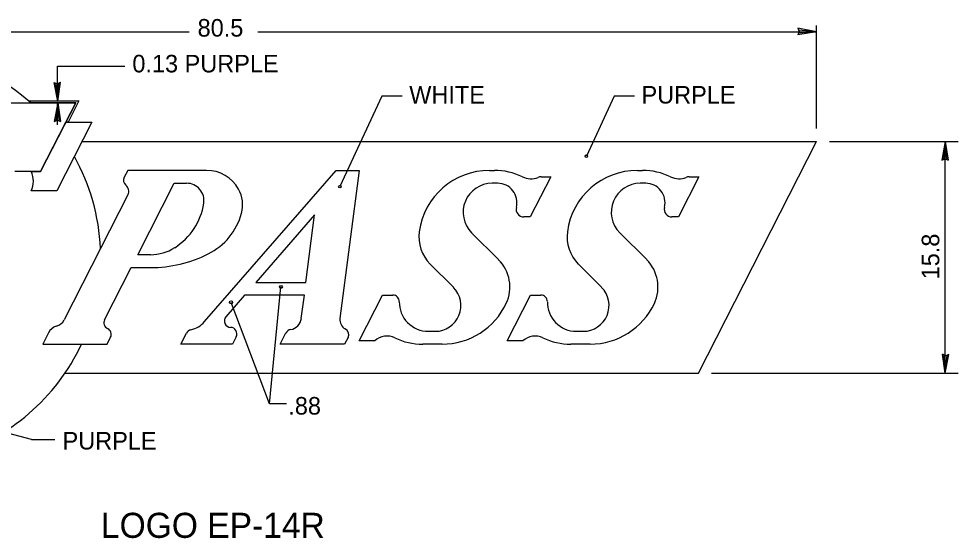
# Model space of a CAD drawing. Extents: x 10268197 to 10268826, y 2141503 to 2142677.
# Drawn here: x 10268696.97 to 10268729.24, y 2142372.5 to 2142390.35 of the extents above; entities that cross this region are included whole.
import ezdxf

# ---------------------------------------------------------------- set-up
doc = ezdxf.new("R2010")
doc.units = 0
for name, color, linetype in [('1', 7, 'Continuous'), ('Default', 7, 'Continuous'), ('TextDetails', 7, 'Continuous')]:
    doc.layers.add(name, color=color, linetype=linetype)

msp = doc.modelspace()

# ---------------------------------------------------------------- linework, layer by layer
at = {"layer": '1'}
for p, q in [((10268724.378, 2142386.58), (10268724.378, 2142390.119)), ((10268679.621, 2142389.898), (10268702.823, 2142389.898)), ((10268705.178, 2142389.898), (10268724.378, 2142389.898)), ((10268698.301, 2142388.721), (10268700.608, 2142388.721)), ((10268698.301, 2142387.55), (10268698.301, 2142388.721)), ((10268698.301, 2142386.707), (10268698.301, 2142387.47)), ((10268709.441, 2142387.689), (10268708.001, 2142384.581)), ((10268710.143, 2142387.689), (10268709.441, 2142387.689)), ((10268717.421, 2142387.689), (10268716.467, 2142385.63)), ((10268718.124, 2142387.689), (10268717.421, 2142387.689)), ((10268724.82, 2142386.137), (10268729.245, 2142386.137)), ((10268728.802, 2142378.174), (10268728.802, 2142386.137)), ((10268705.586, 2142377.117), (10268705.973, 2142381.135)), ((10268705.586, 2142377.117), (10268704.258, 2142380.606)), ((10268720.762, 2142378.174), (10268729.245, 2142378.174)), ((10268706.159, 2142377.117), (10268705.586, 2142377.117)), ((10268697.402, 2142375.891), (10268695.13, 2142376.486)), ((10268697.402, 2142375.891), (10268698.203, 2142375.891))]:
    msp.add_line(p, q, dxfattribs=at)
for centre, radius in [((10268716.467, 2142385.63), 0.0442), ((10268708.001, 2142384.581), 0.0442), ((10268705.973, 2142381.136), 0.0518), ((10268704.258, 2142380.606), 0.0518)]:
    msp.add_circle(centre, radius, dxfattribs=at)
at = {"layer": 'Default'}
for p, q in [((10268724.378, 2142389.898), (10268723.735, 2142390.023)), ((10268723.735, 2142390.023), (10268723.782, 2142389.908)), ((10268724.378, 2142389.898), (10268723.759, 2142389.963)), ((10268723.782, 2142389.908), (10268723.731, 2142389.795)), ((10268724.378, 2142389.898), (10268723.731, 2142389.795)), ((10268724.378, 2142389.898), (10268723.758, 2142389.855)), ((10268698.302, 2142387.519), (10268698.178, 2142388.162)), ((10268698.178, 2142388.162), (10268698.292, 2142388.114)), ((10268698.302, 2142387.519), (10268698.238, 2142388.137)), ((10268698.292, 2142388.114), (10268698.405, 2142388.166)), ((10268698.302, 2142387.519), (10268698.405, 2142388.166)), ((10268698.302, 2142387.519), (10268698.346, 2142388.138)), ((10268691.401, 2142387.465), (10268698.922, 2142387.465)), ((10268697.306, 2142387.531), (10268699.03, 2142387.531)), ((10268698.922, 2142387.465), (10268697.717, 2142385.099)), ((10268698.302, 2142387.466), (10268698.178, 2142386.823)), ((10268698.302, 2142387.466), (10268698.238, 2142386.848)), ((10268698.302, 2142387.466), (10268698.405, 2142386.819)), ((10268698.302, 2142387.466), (10268698.346, 2142386.847)), ((10268699.03, 2142387.531), (10268698.658, 2142386.801)), ((10268697.716, 2142385.097), (10268698.585, 2142386.801)), ((10268697.716, 2142385.097), (10268698.585, 2142386.801)), ((10268698.178, 2142386.823), (10268698.292, 2142386.87)), ((10268699.478, 2142386.801), (10268698.273, 2142384.435)), ((10268699.478, 2142386.801), (10268698.273, 2142384.435)), ((10268698.292, 2142386.87), (10268698.405, 2142386.819)), ((10268698.585, 2142386.801), (10268699.478, 2142386.801)), ((10268698.585, 2142386.801), (10268699.478, 2142386.801)), ((10268699.139, 2142386.137), (10268724.378, 2142386.137)), ((10268720.32, 2142378.174), (10268724.378, 2142386.137)), ((10268728.802, 2142386.137), (10268728.677, 2142385.495)), ((10268728.802, 2142386.137), (10268728.737, 2142385.519)), ((10268728.802, 2142386.137), (10268728.905, 2142385.49)), ((10268728.802, 2142386.137), (10268728.846, 2142385.518)), ((10268728.677, 2142385.495), (10268728.792, 2142385.542)), ((10268728.792, 2142385.542), (10268728.905, 2142385.49)), ((10268700.708, 2142385.142), (10268700.587, 2142384.906)), ((10268703.417, 2142385.142), (10268700.708, 2142385.142)), ((10268703.349, 2142379.946), (10268707.867, 2142385.142)), ((10268707.867, 2142385.142), (10268708.664, 2142385.142)), ((10268708.664, 2142385.142), (10268708.001, 2142380.05)), ((10268713.139, 2142385.142), (10268713.306, 2142385.142)), ((10268718.227, 2142385.142), (10268718.394, 2142385.142)), ((10268697.717, 2142385.099), (10268696.832, 2142385.099)), ((10268697.387, 2142385.097), (10268697.716, 2142385.097)), ((10268697.387, 2142385.097), (10268697.716, 2142385.097)), ((10268715.243, 2142384.92), (10268714.54, 2142383.541)), ((10268714.911, 2142384.92), (10268715.243, 2142384.92)), ((10268720.331, 2142384.92), (10268719.628, 2142383.541)), ((10268719.999, 2142384.92), (10268720.331, 2142384.92)), ((10268701.055, 2142382.244), (10268702.307, 2142384.699)), ((10268702.307, 2142384.699), (10268702.733, 2142384.699)), ((10268713.419, 2142384.699), (10268713.229, 2142384.699)), ((10268718.507, 2142384.699), (10268718.317, 2142384.699)), ((10268698.273, 2142384.435), (10268697.388, 2142384.435)), ((10268698.273, 2142384.435), (10268697.388, 2142384.435)), ((10268700.716, 2142384.305), (10268698.525, 2142380.006)), ((10268707.126, 2142383.616), (10268705.107, 2142381.292)), ((10268706.824, 2142381.292), (10268707.126, 2142383.616)), ((10268714.54, 2142383.541), (10268714.319, 2142383.541)), ((10268719.628, 2142383.541), (10268719.407, 2142383.541)), ((10268712.525, 2142383), (10268713.452, 2142382.073)), ((10268717.613, 2142383), (10268718.54, 2142382.073)), ((10268701.493, 2142382.244), (10268701.055, 2142382.244)), ((10268711.9, 2142381.122), (10268711.104, 2142381.918)), ((10268716.988, 2142381.122), (10268716.192, 2142381.918)), ((10268699.915, 2142380.006), (10268700.829, 2142381.801)), ((10268700.829, 2142381.801), (10268701.493, 2142381.801)), ((10268705.107, 2142381.292), (10268706.824, 2142381.292)), ((10268704.723, 2142380.85), (10268704.082, 2142380.113)), ((10268706.779, 2142380.85), (10268704.723, 2142380.85)), ((10268706.674, 2142380.05), (10268706.779, 2142380.85)), ((10268708.661, 2142379.28), (10268709.464, 2142380.857)), ((10268709.464, 2142380.857), (10268709.819, 2142380.857)), ((10268713.748, 2142379.28), (10268714.552, 2142380.857)), ((10268714.552, 2142380.857), (10268714.907, 2142380.857)), ((10268697.987, 2142379.559), (10268697.788, 2142379.169)), ((10268700, 2142379.169), (10268700.12, 2142379.406)), ((10268702.535, 2142379.169), (10268702.728, 2142379.547)), ((10268704.436, 2142379.424), (10268704.305, 2142379.169)), ((10268705.95, 2142379.169), (10268706.145, 2142379.553)), ((10268708.278, 2142379.397), (10268708.162, 2142379.169)), ((10268711.035, 2142379.611), (10268711.274, 2142379.611)), ((10268716.123, 2142379.611), (10268716.362, 2142379.611)), ((10268697.788, 2142379.169), (10268700, 2142379.169)), ((10268704.305, 2142379.169), (10268702.535, 2142379.169)), ((10268708.162, 2142379.169), (10268705.95, 2142379.169)), ((10268709.198, 2142379.28), (10268708.661, 2142379.28)), ((10268711.512, 2142379.169), (10268710.847, 2142379.169)), ((10268714.286, 2142379.28), (10268713.748, 2142379.28)), ((10268716.6, 2142379.169), (10268715.934, 2142379.169)), ((10268728.802, 2142378.174), (10268728.699, 2142378.82)), ((10268728.812, 2142378.769), (10268728.699, 2142378.82)), ((10268728.802, 2142378.174), (10268728.759, 2142378.793)), ((10268728.802, 2142378.174), (10268728.927, 2142378.816)), ((10268728.802, 2142378.174), (10268728.866, 2142378.791)), ((10268728.927, 2142378.816), (10268728.812, 2142378.769)), ((10268698.553, 2142378.174), (10268720.32, 2142378.174))]:
    msp.add_line(p, q, dxfattribs=at)
msp.add_lwpolyline([(10268697.306, 2142387.531), (10268699.03, 2142387.531), (10268698.658, 2142386.801), (10268698.585, 2142386.801), (10268698.922, 2142387.465), (10268697.382, 2142387.464)], close=True, dxfattribs=at)
for centre, radius, start, end in [((10268692.7, 2142382.155), 7.079, 48.5904, 217.4727), ((10268692.7, 2142382.155), 7.079, 2.4236, 29.2771), ((10268703.417, 2142383.88), 1.261, 29.4315, 90), ((10268713.138, 2142382.708), 2.433, 90, 172.3089), ((10268713.306, 2142382.929), 2.212, 64.0896, 90), ((10268718.226, 2142382.708), 2.433, 90, 172.3089), ((10268718.394, 2142382.929), 2.212, 64.0896, 90), ((10268696.761, 2142384.765), 0.708, 332.2089, 27.9127), ((10268696.761, 2142384.765), 0.708, 332.2089, 27.9127), ((10268700.784, 2142384.805), 0.221, 152.9784, 231.1602), ((10268714.563, 2142385.516), 0.664, 244.0896, 292.0347), ((10268714.911, 2142384.654), 0.265, 90, 112.0347), ((10268719.651, 2142385.516), 0.664, 244.0896, 292.0347), ((10268719.999, 2142384.654), 0.265, 90, 112.0347), ((10268700.479, 2142384.425), 0.265, 333.0027, 51.1602), ((10268702.733, 2142384.101), 0.597, 351.076, 90), ((10268703.552, 2142383.956), 1.106, 344.7074, 29.4315), ((10268713.229, 2142383.703), 0.995, 90, 225), ((10268713.419, 2142384.035), 0.664, 345.6915, 90), ((10268718.317, 2142383.703), 0.995, 90, 225), ((10268718.507, 2142384.035), 0.664, 345.6915, 90), ((10268701.137, 2142384.352), 2.212, 302.4206, 351.076), ((10268714.319, 2142383.805), 0.265, 165.6915, 270), ((10268719.407, 2142383.805), 0.265, 165.6915, 270), ((10268702.485, 2142384.248), 2.212, 296.6431, 344.7074), ((10268712.042, 2142382.856), 1.327, 172.3089, 225), ((10268717.13, 2142382.856), 1.327, 172.3089, 225), ((10268701.493, 2142383.792), 1.548, 270, 302.4206), ((10268701.493, 2142386.225), 4.424, 270, 296.6431), ((10268712.514, 2142381.133), 1.327, 334.95, 45), ((10268717.602, 2142381.133), 1.327, 334.95, 45), ((10268711.274, 2142380.496), 0.885, 270, 45), ((10268716.362, 2142380.496), 0.885, 270, 45), ((10268709.819, 2142380.635), 0.221, 358.6664, 90), ((10268711.036, 2142380.606), 0.995, 178.6665, 270), ((10268714.907, 2142380.635), 0.221, 358.6664, 90), ((10268716.123, 2142380.606), 0.995, 178.6665, 270), ((10268711.512, 2142381.602), 2.433, 270, 334.95), ((10268716.6, 2142381.602), 2.433, 270, 334.95), ((10268698.131, 2142380.206), 0.442, 286.4317, 332.9959), ((10268700.112, 2142379.905), 0.221, 152.9884, 244.7832), ((10268704.249, 2142379.967), 0.221, 138.9824, 268.6869), ((10268706.236, 2142380.107), 0.442, 279.2397, 352.5632), ((10268708.352, 2142380.004), 0.354, 172.5884, 241.8673), ((10268698.381, 2142379.358), 0.442, 106.4317, 152.9742), ((10268699.923, 2142379.505), 0.221, 333.0239, 64.7832), ((10268702.925, 2142379.446), 0.221, 102.7162, 153.0239), ((10268702.682, 2142380.525), 0.885, 282.7162, 318.9966), ((10268704.238, 2142379.525), 0.221, 332.9784, 88.6869), ((10268706.342, 2142379.452), 0.221, 99.2397, 153.0239), ((10268708.081, 2142379.497), 0.221, 332.9784, 61.8673), ((10268709.622, 2142378.827), 0.619, 64.3795, 133.1892), ((10268710.846, 2142381.381), 2.212, 244.3795, 270), ((10268714.71, 2142378.827), 0.619, 64.3795, 133.1892), ((10268715.934, 2142381.381), 2.212, 244.3795, 270), ((10268692.7, 2142382.155), 7.079, 237.5383, 335.047)]:
    msp.add_arc(centre, radius, start, end, dxfattribs=at)

# ---------------------------------------------------------------- texts
at = {"layer": '1'}
for s, height, p in [('80.5', 0.6037, (10268703.11, 2142389.737)), ('0.13 PURPLE', 0.60368, (10268700.869, 2142388.507)), ('WHITE', 0.6037, (10268710.382, 2142387.437)), ('PURPLE', 0.6037, (10268718.363, 2142387.437)), ('.88', 0.6037, (10268706.227, 2142376.749)), ('PURPLE', 0.6037, (10268698.47, 2142375.549))]:
    msp.add_text(s, height=height, dxfattribs=at).set_placement(p)
msp.add_text('15.8', height=0.6037, rotation=90, dxfattribs=at).set_placement((10268728.594, 2142381.396))
at = {"layer": 'TextDetails'}
msp.add_text('LOGO EP-14R', height=0.8624, dxfattribs=at).set_placement((10268699.789, 2142372.513))

doc.saveas('drawing.dxf')
